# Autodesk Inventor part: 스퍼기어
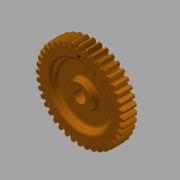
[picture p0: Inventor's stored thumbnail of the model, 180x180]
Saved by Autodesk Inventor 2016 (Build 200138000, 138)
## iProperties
Created: 2019-01
Part Number: 스퍼기어
Material: 알루미늄 6061
Document SubType Name: Modeling
Designer: mduedu
Density: 2.71 g/cm^3
Mass: 157.226 g
Surface Area: 186.47 cm^2
Volume: 58.017 cm^3
Appearance: 주황색
Author: mduedu
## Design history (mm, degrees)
sketch "스케치1"
  geometry: C1 r 37.5 at (0, 0); C2 r 40 at (0, 0); C3 r 42 at (0, 0); 1 further point
  constraints: 3 centre point, 3 coincident
  dimensions: "d0" = 75 diameter of C1; "d2" = 80 diameter of C2; "d3" = 84 diameter of C3
extrude "돌출1" new body sketch "스케치1" distance "d4" = 14; taper "d5" = 0 deg
sketch "스케치2"
  geometry: L1 (0, 0)-(-42, 0); L2 (0, 0)-(0, 42); L3 (-0.57, 0)-(-0.57, 41.996); L4 (-1.57, 0)-(-1.57, 39.969); L5 (-2.07, 0)-(-2.07, 37.443); A1 r 42 centre (0, 0) between (-42, 0) and (0, 42) reference; A2 r 9.223 centre (7.138, 36.933) between (-0.57, 41.996) and (-2.07, 37.443); A3 r 9.223 centre (-7.138, 36.933) between (2.07, 37.443) and (0.57, 41.996); A4 r 37.5 centre (0, 0) between (2.07, 37.443) and (-2.07, 37.443); A5 r 42 centre (0, 0) between (0.57, 41.996) and (-0.57, 41.996); 2 further points
  constraints: 12 point on circle, 10 end point, 4 centre point, 3 parallel, 3 symmetric about line, 2 coincident, 1 horizontal, 1 perpendicular, 5 other
  dimensions: "d6" = 0.5 distance between parallel lines of L4 L5; "d8" = 1 distance between parallel lines of L3 L4; "d9" = 1.57 distance between parallel lines of L2 L4
extrude "돌출2" join sketch "스케치2" stored distance "d10" = 14; taper "d11" = 0 deg
chamfer "모따기1" distance "d12" = 1; stored, may be unused: second distance "d13" = 2, angle "d14" = 45 deg
fillet "모깎기1" dims "d15" = 0.5
sketch "스케치3"
  geometry: C1 r 11 at (0, 0); 1 further point
  constraints: 1 centre point, 1 coincident
  dimensions: "d19" = 22 diameter of C1
extrude "돌출3" join sketch "스케치3" distance "d20" = 7; taper "d21" = 0 deg
fillet "모깎기2" dims "d22" = 3
sketch "스케치4"
  geometry: C1 r 11 at (0, 0); C2 r 27.5 at (0, 0); 1 further point
  constraints: 2 centre point, 2 coincident
  dimensions: "d23" = 22 diameter of C1; "d24" = 55 diameter of C2
extrude "돌출4" cut sketch "스케치4" distance "d25" = 6; taper "d26" = 0 deg
fillet "모깎기3" dims "d27" = 3
sketch "스케치5" dims "d28" = 66
  geometry: C1 r 1.5 at (0, 33); 2 further points
  constraints: 2 vertical alignment, 1 centre point, 1 coincident, 2 other
  dimensions: "d29" = 3 diameter of C1
extrude "돌출5" join sketch "스케치5" distance "d30" = 0.5; taper "d31" = 0 deg
sketch "스케치6"
  geometry: L1 (-2, 5.657)-(2, 5.657); L2 (2, 5.657)-(2, 7.8); L3 (2, 7.8)-(-2, 7.8); L4 (-2, 7.8)-(-2, 5.657); A1 r 6 centre (0, 0) between (-2, 5.657) and (2, 5.657); 1 further point
  constraints: 8 end point, 2 parallel, 2 point on circle, 1 centre point, 1 coincident, 1 horizontal, 1 perpendicular
  dimensions: "d32" = 13.8 dimension on A1 L3; "d34" = 4 distance of L2.end L3.end; "d35" = 12 diameter of A1
extrude "돌출6" cut sketch "스케치6" stored distance "d36" = 0.5; taper "d37" = 0 deg
chamfer "모따기2" distance "d38" = 1; stored, may be unused: second distance "d39" = 2, angle "d40" = 45 deg
node "솔리드1"
pattern_circular "원형 패턴1" dims "d17" = 360 deg
